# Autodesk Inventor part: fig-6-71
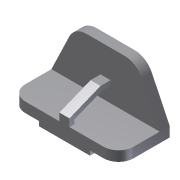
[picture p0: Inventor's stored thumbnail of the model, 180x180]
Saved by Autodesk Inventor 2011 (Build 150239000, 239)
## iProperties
Shininess: 77.0
Length Units: 11269
Angle Units: 11279
Time Units: 11290
Mass Units: 11283
Length Display Precision: 3
Angle Display Precision: 2
Created: 2001-12
Part Number: fig-6-71
Document SubType Name: Modeling
Designer: Renu Muthoo
Density: 1 g/cm^3
Density: 0.0
Volumn: 0.0
Area: 0.0
PropertySet Name: Model Information
Control State: 0
Master: False
Checked Out: False
Author: Renu Muthoo
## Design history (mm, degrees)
sketch "Sketch2"
  geometry: L1 (-67.219, 19.116)-(148.781, 19.116); L2 (148.781, 19.116)-(148.781, -0.884); L3 (-67.219, -0.884)-(-67.219, 19.116); L4 (-10.219, -0.884)-(-10.219, -9.884); L5 (-10.219, -9.884)-(91.781, -9.884); L6 (91.781, -9.884)-(91.781, -0.884); L7 (148.781, -0.884)-(91.781, -0.884); L8 (-10.219, -0.884)-(-67.219, -0.884)
  constraints: 16 end point, 5 parallel, 4 perpendicular, 2 equal length, 1 horizontal
  dimensions: "d0" = 102 distance of L4.end L5.end; "d1" = 57 distance of L4.start L3.start; "d2" = 29 distance between parallel lines of L1 L5; "d3" = 20 distance of L1.end L2.end
extrude "Extrusion1" new body sketch "Sketch2" distance "d4" = 102; taper "d5" = 0 deg
sketch "Sketch3"
  geometry: L1 (67.219, -19.116)-(-148.781, -19.116) reference; L2 (67.219, -19.116)-(31.475, -93.564); L3 (-2.781, -115.116)-(-78.781, -115.116); L4 (-113.038, -93.564)-(-148.781, -19.116); A1 r 38 centre (-2.781, -77.116) between (-2.781, -115.116) and (31.475, -93.564); A2 r 38 centre (-78.781, -77.116) between (-113.038, -93.564) and (-78.781, -115.116)
  constraints: 6 end point, 4 point on circle, 4 tangent, 2 centre point, 1 equal length, 1 equal radius, 1 parallel
  dimensions: "d6" = 96 distance between parallel lines of L3 L1; "d7" = 38 radius of A1; "d8" = 76 distance of A2.centre A1.centre
extrude "Extrusion2" join sketch "Sketch3" distance "d9" = 20; taper "d10" = 0 deg
fillet "Fillet1" dims "d11" = 30
workplane "Work Plane1"
sketch "Sketch7"
  geometry: L1 (0, -82)-(-15, -82); L2 (-15, -82)-(-40, -20); L3 (-40, -20)-(-40, 0); L4 (0, -82)-(20, -82) reference; L5 (0, 0)-(-74.447, 0) reference
  constraints: 6 end point, 2 point on line, 1 horizontal, 1 perpendicular
  dimensions: "d32" = 20 distance of L2.end L3.end; "d33" = 15 distance of L1.start L1.end; "d34" = 40 distance of L5.start L3.end
feature "Rib4" sketch "Sketch7" dims "d55" = 10, "d56" = 20, "d57" = 0
body "Solid1"
other parameters: "d12" = -108
